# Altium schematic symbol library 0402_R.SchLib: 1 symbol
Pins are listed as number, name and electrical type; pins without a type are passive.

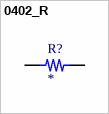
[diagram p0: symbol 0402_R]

## 0402_R
designator R?
footprint 0402
pins: 1, 2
